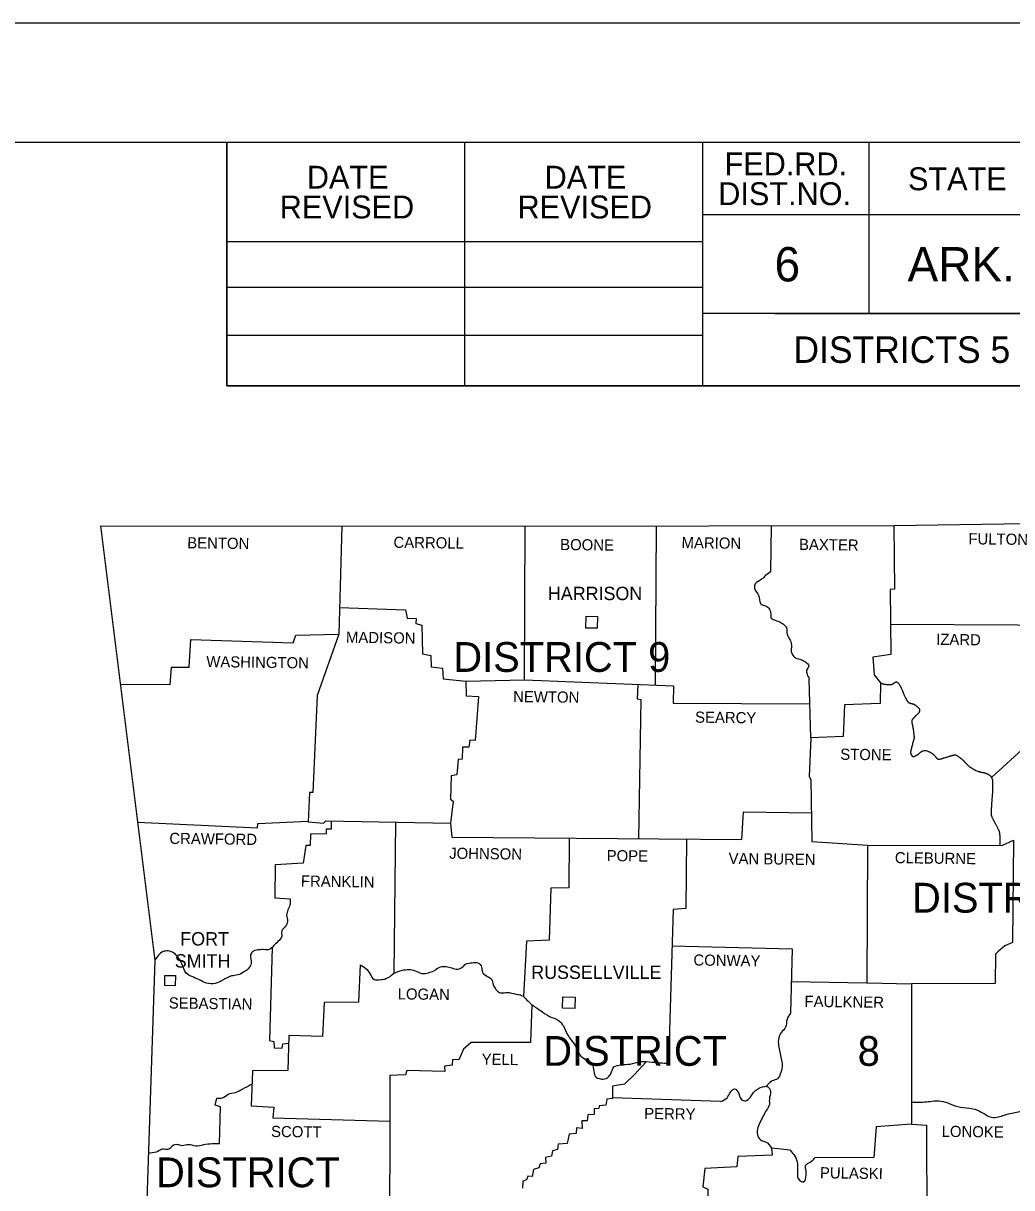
# Model space of a CAD drawing. Extents: x -819161 to 80911, y -6604 to 768454.
# Drawn here: x 48407 to 50478, y 8220 to 10660 of the extents above; entities that cross this region are included whole.
import ezdxf

# ---------------------------------------------------------------- set-up
doc = ezdxf.new("R2010")
doc.units = 0
for name, color, linetype in [('Default', 7, 'Continuous'), ('DSN_DRFT_Junk-No-Plot', 7, 'Continuous'), ('SHET_Annotations', 7, 'Continuous'), ('SHET_Border-Lines', 7, 'Continuous'), ('SHET_Border-Text', 7, 'Continuous')]:
    doc.layers.add(name, color=color, linetype=linetype)

msp = doc.modelspace()

# ---------------------------------------------------------------- linework, layer by layer
at = {"layer": 'Default'}
for p, q in [((49965.8, 8435), (49963.8, 8432.9)), ((48673, 8293.1), (48669, 8292.6))]:
    msp.add_line(p, q, dxfattribs=at)
for points in [[(35278.1, 10659.9), (35278.1, -340.1), (52278.1, -340.1), (52278.1, 10659.9)], [(49585.8, 9392.9), (49586.4, 9417.8), (49610, 9417.2), (49609.4, 9392.3)], [(48703.2, 8644.1), (48703.8, 8665.3), (48725.6, 8664.7), (48725, 8643.5)], [(49536.6, 8596.2), (49537.2, 8620.5), (49563.1, 8619.8), (49562.4, 8595.6)]]:
    msp.add_lwpolyline(points, close=True, dxfattribs=at)
for points in [[(48569, 9606.7), (49454.1, 9606.1), (50231.5, 9607.6), (51148, 9621.6), (51573.2, 9631.6)], [(50695.2, 9614.7), (50696.2, 9476.9), (50624.9, 9472.9), (50623, 9398.5), (50224.1, 9400.4)], [(48569, 9606.7), (48682.3, 8696.4), (48633.2, 7210.7)], [(49074.2, 9606.3), (49068.4, 9379.9)], [(49069.8, 9435.6), (49208, 9431.2), (49211.1, 9413.7), (49230.1, 9413.1), (49229.4, 9402.5), (49242.2, 9399.1), (49243.4, 9339.1), (49260.6, 9335.3), (49261.8, 9311.7), (49285.5, 9308.6), (49286.7, 9286.5), (49334, 9281.3), (49457.2, 9284.6), (49458.2, 9606.1)], [(49732.7, 9606.6), (49730.8, 9273.1)], [(49973.6, 9607.1), (49972.3, 9510.5)], [(50231.2, 9607.6), (50232.5, 9474.1), (50223.4, 9473.5), (50224.7, 9337.2), (50186.7, 9331.6), (50189.8, 9295.2), (50202.9, 9278.1), (50202, 9234.8), (50127.6, 9232), (50124.8, 9165.4), (50056.9, 9163.2), (50053.2, 9081.7), (50057.3, 9075.5), (50059.1, 8946), (50175.8, 8938.2), (50174.3, 8649.7), (50267.6, 8647.2), (50267.6, 8353.4), (50194.2, 8347.8), (50188.9, 8283.7), (50065.3, 8282.8)], [(48610.3, 9275.3), (48714.7, 9274.9), (48717.2, 9310.7), (48754.8, 9310.7), (48758.3, 9369.2), (48972.1, 9361.8), (48978.3, 9378), (49068.4, 9379.9), (49022.5, 9251.6), (49013.5, 9048.4), (49006.9, 9048.1), (49003.8, 8986.8), (49035.9, 8984), (49040.8, 8988.9), (49301.9, 8984), (49304.7, 8955)], [(49334, 9281.3), (49335.2, 9251), (49360.5, 9249.7), (49353.9, 9157.6), (49342.4, 9157.9), (49340.2, 9143.3), (49327.2, 9143), (49326.5, 9118.1), (49318.4, 9117.5), (49315.6, 9085.1), (49303.5, 9083.5), (49301.9, 9034.4), (49307.5, 9030.3), (49301.9, 8984)], [(49457.2, 9284.6), (49769.1, 9271.5), (49768.8, 9235.7), (50055.2, 9233.9)], [(49694.4, 9274.6), (49693.4, 9244.8), (49700.9, 9242.9), (49696.2, 8951.6)], [(50056.9, 9163.2), (50053.8, 9286.1)], [(50435.8, 9079.7), (50499.2, 9137.4), (50696.2, 9134.3), (50699.9, 9097.9), (50772.4, 9100.7)], [(49304.7, 8955), (49912.5, 8949.7), (49915.7, 9007.6), (50058.3, 9005.7)], [(48646.3, 8986.2), (48897.4, 8974.3), (48898.6, 8983.3), (49003.9, 8988.1)], [(49052.3, 8988.7), (49051.7, 8971.8), (49041.5, 8971.8), (49041.8, 8961.9), (49008.8, 8961.2), (49008.2, 8937), (48998.8, 8937), (48993.5, 8900.2), (48934.4, 8897.1), (48934.1, 8828), (48965.8, 8825.6)], [(49187.1, 8986.2), (49183.1, 8669.9)], [(49550.6, 8952.9), (49550, 8848.3), (49512.3, 8847.7), (49508.9, 8738.7), (49461, 8736.9), (49455.2, 8620.9)], [(49796.2, 8950.7), (49795.2, 8805.6), (49768.5, 8803.1), (49758.5, 8481)], [(50175.8, 8938.2), (50457.5, 8937), (50481.4, 8948.2), (50479.9, 8734.4), (50463.7, 8727.2), (50448.8, 8714.5), (50444.1, 8709.5), (50443.2, 8648.2), (50267.6, 8647.2)], [(48928.7, 8723.8), (48922.9, 8528.7), (48931.6, 8526.5), (48932.8, 8513.4), (48949.7, 8512.5), (48950.9, 8521.5), (48962.9, 8523.5)], [(49766.1, 8727.3), (50017.7, 8721), (50014.6, 8585.9)], [(49112.7, 8687.4), (49109, 8609.3), (49037.7, 8608.6), (49033.7, 8537.4), (48963.3, 8539.2), (48961.2, 8466.1), (48887.1, 8465.2), (48884.6, 8391.7), (48931.6, 8389.2), (48929.7, 8366.5), (49174.7, 8359.8)], [(50016.1, 8652.2), (50174.3, 8649.7)], [(49472.5, 8603.7), (49470, 8524.9), (49345.5, 8524.3), (49329, 8510.3), (49319.4, 8488.5), (49306, 8489.1), (49305.4, 8477), (49289.5, 8475.1), (49290.1, 8463.9), (49210.8, 8465.8), (49207.6, 8457.1), (49175, 8455.8), (49174.7, 8359.8)], [(49712.2, 8484.3), (49687.5, 8457.7), (49666.4, 8437.5), (49641.5, 8433.4), (49641.8, 8407.6), (49629.7, 8406), (49627.5, 8393), (49613.5, 8391.7), (49612.8, 8386.1), (49603.2, 8385.5), (49602.9, 8374), (49589.5, 8373.4), (49588.6, 8360.3), (49577.4, 8360.3), (49578, 8344.7), (49566.2, 8346), (49565.2, 8333.8), (49550.6, 8332.9), (49546.6, 8313), (49527.9, 8311.4), (49526, 8300.2), (49516.1, 8297.7), (49513.6, 8286.2), (49501.1, 8283.7), (49502.1, 8271.9), (49489.6, 8270.7), (49487.4, 8262), (49475.9, 8258.8), (49473.1, 8243.9), (49464.1, 8244.8), (49461.6, 8237.1), (49453.5, 8234.3), (49452.6, 8219.3)], [(48818.3, 8312.4), (48820.2, 8389.5), (48809, 8393.3), (48812.7, 8407.9)], [(49868, 8401.1), (49641.8, 8408.6)], [(49174.7, 8359.8), (49174, 8135.6), (49146.3, 8135), (49148.8, 8118.8), (49122.4, 8119.1), (49121.8, 8107), (49095.9, 8107), (49096.5, 8098.6), (49058.6, 8097.3), (49057.6, 8064), (49020.6, 8067.4), (49014.4, 7797.9)], [(50267.6, 8353.4), (50299.4, 8351.6), (50300, 8142.1), (50271.4, 8023.6), (50332.4, 8020.5), (50331.4, 7916)], [(50014, 8298.7), (49974.8, 8303.3), (49976.3, 8288.4), (49904.4, 8285.6), (49902.3, 8264.4), (49834.7, 8260.7), (49831, 8222.1), (49841, 8217.1), (49841, 8191.9)]]:
    msp.add_lwpolyline(points, dxfattribs=at)
for points in [[(49972.3, 9510.5), (49962.3, 9502.8), (49953.9, 9495), (49940.6, 9485.3), (49939, 9476.6), (49943.4, 9468.2), (49947.7, 9461), (49949.6, 9451.1), (49953.3, 9443), (49962.3, 9439.3), (49970.4, 9432.4), (49972.9, 9422.8), (49974.2, 9413.4), (49982.6, 9409.1), (49992.5, 9405.3), (50002.2, 9398.8), (50006.5, 9391), (50007.1, 9380.1), (50011.2, 9372.4), (50015.6, 9362.1), (50016.5, 9354), (50015.6, 9345.9), (50018, 9338.1), (50024.9, 9330.3), (50037.3, 9326.6), (50046.4, 9321.3), (50052.6, 9313.5), (50048.2, 9304.5), (50049.2, 9296.1), (50053.8, 9286.1)], [(48965.8, 8825.6), (48965.8, 8814), (48961.5, 8802.2), (48958.7, 8791.6), (48960.5, 8777.9), (48955.6, 8767), (48948.4, 8758), (48948.4, 8747.4), (48940.3, 8735.9), (48931.3, 8726.9), (48923.8, 8720.1), (48909.8, 8719.1), (48898.3, 8718.5), (48887.1, 8714.5), (48882.7, 8706), (48884.6, 8693.6), (48880.3, 8681.5), (48869.1, 8672.4), (48856.3, 8666.2), (48843.2, 8664), (48824.9, 8655.3), (48808.7, 8648.5), (48790.9, 8649.1), (48774.8, 8656.3), (48759.8, 8662.8), (48748.3, 8669.6), (48739.3, 8689.6), (48733.1, 8700.8), (48722.5, 8712), (48710.3, 8716.3), (48699.8, 8715.1), (48682.3, 8696.4)], [(49112.7, 8687.4), (49124.6, 8679.9), (49133.9, 8667.5), (49142, 8656.9), (49156, 8656.3), (49166.9, 8658.4), (49183.1, 8669.9)], [(49183.1, 8669.9), (49201.4, 8675.9), (49214.5, 8677.4), (49227.9, 8674.9), (49241.6, 8669.3), (49255.9, 8670.9), (49266.8, 8674.6), (49278, 8681.8), (49289.8, 8684), (49301.6, 8681.8), (49313.8, 8678.4), (49326.5, 8682.4), (49334.3, 8689.2), (49347.4, 8691.7), (49359.2, 8691.7), (49367.3, 8682.4), (49368.9, 8672.1), (49379.4, 8663.1), (49388.5, 8656.9), (49391.6, 8645.7), (49396.2, 8637.3), (49401.2, 8631.7), (49408.4, 8628.6), (49420.5, 8629.5), (49439.2, 8625.8), (49451, 8623.3), (49462.2, 8613.6), (49472.5, 8603.7)], [(49472.5, 8603.7), (49491.8, 8590.6), (49509.8, 8579.1), (49528.2, 8571), (49538.5, 8559.2), (49547.8, 8540.2), (49555.9, 8528.7), (49565.2, 8514.3), (49572.7, 8498.8), (49583.9, 8489.8), (49596, 8482.3), (49602, 8468.6), (49604.8, 8454.9), (49618.1, 8448.1), (49630.9, 8450.9), (49637.7, 8459.3), (49644.6, 8473.3), (49659.2, 8477.9), (49678.2, 8479.5), (49700, 8484.5), (49724.6, 8483.5), (49758.5, 8481)], [(50014.6, 8585.9), (50007.1, 8573.2), (50004.3, 8556.7), (49995.3, 8546.1), (49989.7, 8534.6), (49989.4, 8518.4), (49991.9, 8504.1), (49994.7, 8490.7), (49997.2, 8477.9), (49994.1, 8462.1), (49986.9, 8448.4), (49976.3, 8444.3), (49965.8, 8435)], [(48812.7, 8407.9), (48824.5, 8408.8), (48836.1, 8416.3), (48851.3, 8420), (48866.9, 8427.8), (48886.1, 8437.1)], [(49868, 8401.1), (49881.4, 8408.8), (49888.6, 8420.4), (49897.3, 8427.5), (49906, 8417.6), (49913.8, 8403.6), (49922.2, 8403.2), (49932.5, 8413.5), (49939, 8422.2), (49947.4, 8428.4), (49956.1, 8431.6), (49965.1, 8432.5), (49972.6, 8421.9), (49970.1, 8405.4), (49970.1, 8394.8), (49964.2, 8383), (49957.4, 8370.9), (49950.5, 8357.2), (49945.2, 8342.9), (49946.2, 8328.2), (49953.9, 8319.2), (49962.3, 8316.4), (49974.8, 8303.3)], [(50267.6, 8399.8), (50299.1, 8400.4), (50329.3, 8402), (50348.5, 8396.1), (50370.3, 8389.2), (50396.5, 8385.8), (50414.2, 8379), (50435.7, 8368.1), (50463.1, 8372.7), (50484.5, 8378), (50512.6, 8385.2), (50530.3, 8393.3), (50551.1, 8399.5), (50572, 8397), (50595.6, 8392.3), (50610.3, 8383.6), (50637.4, 8387.4), (50637.4, 8421.3)], [(48818.3, 8312.4), (48802.8, 8312.1), (48784.4, 8309.9), (48767.9, 8307.7), (48753.3, 8310.5), (48739.9, 8308.3), (48730.6, 8310.5), (48719, 8307.7), (48712.2, 8300.9), (48698.5, 8300.9), (48688.9, 8296.5), (48673, 8293.1)], [(50014, 8298.7), (50023.3, 8286.8), (50028.9, 8270.4), (50028.9, 8251.7), (50033, 8236.4), (50042, 8233), (50047.3, 8246.4), (50046.4, 8259.2), (50046.1, 8267.2), (50055.7, 8273.8), (50065.3, 8282.8)]]:
    msp.add_spline(points, degree=3, dxfattribs=at)
msp.add_open_spline([(50202.9, 9278.1), (50204.6, 9277.2), (50206.4, 9276.5), (50208.2, 9276.1), (50210.1, 9275.6), (50211.9, 9275.2), (50213.7, 9275), (50215.6, 9274.8), (50217.4, 9274.7), (50219.2, 9274.5), (50221.1, 9274.4), (50222.9, 9274.3), (50224.7, 9274.3), (50225.9, 9274.3), (50227.1, 9274.8), (50228.2, 9275.5), (50229.4, 9276.2), (50230.4, 9277.2), (50231.6, 9278), (50232.7, 9278.7), (50233.8, 9279.3), (50234.9, 9279.9), (50235.4, 9280.1), (50236, 9280.1), (50236.5, 9280), (50237.1, 9279.9), (50237.6, 9279.7), (50238.1, 9279.3), (50240.5, 9277.2), (50242.2, 9275.1), (50243.6, 9272.5), (50244.3, 9271.2), (50245, 9269.9), (50245.6, 9268.6), (50246.2, 9267.3), (50246.8, 9266), (50247.4, 9264.7), (50249, 9261.1), (50250.5, 9257.4), (50252.1, 9253.8), (50253.3, 9251.1), (50254.5, 9248.4), (50255.8, 9245.8), (50256.5, 9244.5), (50257.2, 9243.2), (50257.9, 9241.9), (50258.3, 9241.3), (50258.7, 9240.7), (50259.2, 9240), (50259.6, 9239.4), (50260, 9238.8), (50260.5, 9238.2), (50261.2, 9237.3), (50262.1, 9236.6), (50263.2, 9236.1), (50264.3, 9235.7), (50265.4, 9235.4), (50266.6, 9235.1), (50267.8, 9234.8), (50269, 9234.6), (50270.2, 9234.3), (50270.8, 9234.1), (50271.4, 9233.9), (50271.9, 9233.7), (50272.5, 9233.5), (50273, 9233.2), (50273.5, 9232.9), (50275.4, 9231.8), (50277.2, 9230.6), (50278.9, 9229.2), (50279.8, 9228.5), (50280.6, 9227.8), (50281.4, 9227), (50282.1, 9226.2), (50282.8, 9225.4), (50283.5, 9224.5), (50284, 9223.9), (50284.3, 9223.1), (50284.5, 9222.3), (50284.8, 9221.5), (50284.8, 9220.6), (50284.8, 9219.8), (50284.7, 9218.6), (50284.4, 9217.4), (50283.8, 9216.2), (50283.6, 9215.8), (50283.4, 9215.5), (50283.2, 9215.2), (50282.5, 9214.4), (50281.9, 9213.6), (50281.2, 9212.9), (50280.4, 9212.2), (50279.6, 9211.5), (50278.9, 9210.8), (50278.1, 9210.1), (50277.4, 9209.5), (50276.6, 9208.7), (50275.8, 9208), (50275.2, 9207.2), (50274.5, 9206.5), (50274.2, 9206.1), (50273.9, 9205.8), (50273.5, 9205.4), (50272.6, 9204.3), (50271.5, 9203.3), (50270.5, 9202.2), (50269.9, 9201.5), (50269.4, 9200.8), (50268.9, 9200), (50268.7, 9199.6), (50268.5, 9199.2), (50268.4, 9198.7), (50268.3, 9198.3), (50268.3, 9197.9), (50268.3, 9197.5), (50268.3, 9196.6), (50268.3, 9195.7), (50268.5, 9194.8), (50268.7, 9193.9), (50268.9, 9193.1), (50269.1, 9192.2), (50269.4, 9191.3), (50269.6, 9190.4), (50269.8, 9189.5), (50270.1, 9188.7), (50270.3, 9187.8), (50270.4, 9186.9), (50270.9, 9184.5), (50271.2, 9182.1), (50271.6, 9179.7), (50272, 9177.3), (50272.3, 9174.9), (50272.6, 9172.6), (50273.2, 9168.1), (50273.6, 9163.5), (50272.6, 9159.2), (50271.6, 9154.9), (50270.3, 9150.7), (50269.2, 9146.4), (50268.2, 9142.7), (50267.3, 9139), (50266.4, 9135.2), (50266.2, 9134.4), (50266.1, 9133.5), (50266.1, 9132.6), (50266.1, 9131.8), (50266.2, 9130.9), (50266.4, 9130), (50266.7, 9129.1), (50267, 9128.3), (50267.4, 9127.5), (50267.7, 9127), (50267.9, 9126.6), (50268.2, 9126.2), (50268.5, 9125.8), (50268.8, 9125.4), (50269.2, 9124.9), (50269.5, 9124.6), (50269.9, 9124.3), (50270.3, 9124), (50270.7, 9123.8), (50271.1, 9123.6), (50271.6, 9123.6), (50272.4, 9123.6), (50273.4, 9123.7), (50274.3, 9124), (50276.1, 9124.9), (50277.8, 9125.8), (50279.5, 9126.8), (50279.9, 9127.1), (50280.4, 9127.4), (50280.9, 9127.7), (50281.4, 9128), (50281.8, 9128.4), (50282.3, 9128.7), (50283.2, 9129.5), (50284, 9130.3), (50284.9, 9131.1), (50285.8, 9131.8), (50286.7, 9132.6), (50287.7, 9133.3), (50288.6, 9134), (50289.6, 9134.5), (50290.7, 9134.9), (50294.3, 9136.2), (50298.6, 9136.3), (50302.2, 9134.9), (50304.1, 9134.2), (50306, 9133.3), (50307.8, 9132.3), (50309.6, 9131.2), (50311.4, 9130.2), (50313.1, 9129), (50314.1, 9128.2), (50315.1, 9127.3), (50315.9, 9126.2), (50316.8, 9125.2), (50317.6, 9124), (50318.5, 9122.9), (50319.3, 9121.9), (50320.1, 9120.9), (50321.1, 9119.9), (50321.5, 9119.5), (50322, 9119.2), (50322.6, 9118.9), (50322.8, 9118.8), (50323.1, 9118.7), (50323.4, 9118.6), (50323.7, 9118.5), (50324, 9118.4), (50324.3, 9118.4), (50326.2, 9118.2), (50328.2, 9118.3), (50330, 9118.9), (50332, 9119.4), (50333.9, 9120), (50335.8, 9120.6), (50339, 9121.6), (50342.2, 9122.7), (50345.4, 9123.7), (50347.6, 9124.4), (50349.8, 9125.1), (50352, 9125.8), (50353, 9126.1), (50354.1, 9126.3), (50355.2, 9126.6), (50355.8, 9126.7), (50356.3, 9126.8), (50356.9, 9126.9), (50357.4, 9127), (50358, 9127.1), (50358.5, 9127.1), (50360.2, 9127.2), (50361.9, 9126.7), (50363.3, 9125.7), (50364.9, 9124.6), (50366.4, 9123.6), (50367.8, 9122.5), (50369.2, 9121.4), (50370.6, 9120.4), (50372, 9119.3), (50373.4, 9118.2), (50374.7, 9117.1), (50375.9, 9115.9), (50376.8, 9115.1), (50377.7, 9114.3), (50378.5, 9113.4), (50379.3, 9112.5), (50380.1, 9111.6), (50380.9, 9110.8), (50381.7, 9109.9), (50382.5, 9109), (50383.3, 9108.1), (50384.1, 9107.3), (50385, 9106.5), (50385.9, 9105.6), (50388.8, 9103), (50391.9, 9100.8), (50395.2, 9098.8), (50399, 9096.5), (50402.9, 9094.5), (50407.1, 9092.9), (50408.3, 9092.4), (50409.5, 9092), (50410.7, 9091.7), (50412, 9091.5), (50413.2, 9091.2), (50414.5, 9090.9), (50415.7, 9090.7), (50417, 9090.5), (50418.3, 9090.2), (50419.5, 9090), (50420.8, 9089.5), (50422, 9089.2), (50424.7, 9088.3), (50427.3, 9087.2), (50429.8, 9085.8), (50431, 9085.1), (50432.1, 9084.3), (50433.1, 9083.3), (50433.6, 9082.8), (50434.1, 9082.3), (50434.5, 9081.7), (50434.7, 9081.4), (50434.9, 9081.1), (50435.1, 9080.8), (50435.3, 9080.5), (50435.5, 9080.1), (50435.7, 9079.8), (50436, 9079.2), (50436.3, 9078.5), (50436.5, 9077.9), (50437.2, 9075.9), (50437.7, 9073.9), (50437.8, 9071.9), (50437.9, 9070.6), (50437.9, 9069.3), (50437.9, 9067.9), (50437.9, 9066.6), (50437.9, 9065.3), (50437.9, 9063.9), (50437.8, 9061.7), (50437.8, 9059.4), (50437.8, 9057.1), (50437.8, 9054.8), (50437.7, 9052.5), (50437.6, 9050.2), (50437.2, 9044.5), (50436.7, 9038.8), (50436.3, 9033.1), (50435.9, 9027), (50435.5, 9020.9), (50435.1, 9014.8), (50435, 9013.2), (50434.8, 9011.7), (50434.7, 9010.1), (50434.6, 9008.6), (50434.6, 9007), (50434.6, 9005.5), (50434.6, 9003.9), (50434.8, 9002.4), (50435.1, 9000.9), (50435.5, 8999.3), (50435.9, 8997.8), (50436.6, 8996.4), (50437.6, 8994.4), (50438.7, 8992.4), (50439.7, 8990.4), (50440.8, 8988.5), (50441.8, 8986.5), (50442.8, 8984.6), (50444.1, 8982.2), (50445.3, 8979.8), (50446.6, 8977.4), (50447.8, 8975.1), (50449.1, 8972.7), (50450.3, 8970.3), (50451.3, 8968.2), (50451.9, 8966), (50452.2, 8963.7), (50452.4, 8962.6), (50452.5, 8961.5), (50452.6, 8960.3), (50452.7, 8959.2), (50452.7, 8958), (50452.8, 8956.9), (50453, 8953.6), (50453.1, 8950.2), (50453.1, 8946.9), (50453, 8943.6), (50452.8, 8940.3), (50452.3, 8937)], degree=3, dxfattribs=at)
at = {"layer": 'DSN_DRFT_Junk-No-Plot'}
msp.add_lwpolyline([(35278.1, -340.1), (52278.1, -340.1), (52278.1, 10659.9), (35278.1, 10659.9)], close=True, dxfattribs=at)
at = {"layer": 'SHET_Border-Lines'}
for p, q in [((48833.5, 9900.4), (48833.5, 10409.9)), ((49331.8, 9900.4), (49331.8, 10409.9)), ((49830, 10409.9), (49830, 9900.4)), ((50178.9, 10409.9), (50178.9, 10052)), ((52028.1, 10258.3), (49830, 10258.3)), ((48833.5, 10202.6), (49830, 10202.6)), ((48833.5, 10106.7), (49830, 10106.7)), ((52028.1, 10052), (49830, 10052)), ((49981, 10052), (52028.1, 10052)), ((48833.5, 10006.7), (49830, 10006.7)), ((52028.1, 9900.4), (48833.5, 9900.4))]:
    msp.add_line(p, q, dxfattribs=at)
for points in [[(35528.1, -90.1), (52028.1, -90.1), (52028.1, 10409.9), (35528.1, 10409.9)], [(35528.1, -90.1), (52028.1, -90.1), (52028.1, 10409.9), (35528.1, 10409.9)], [(48833.5, 9900.4), (52028.1, 9900.4), (52028.1, 10409.9), (48833.5, 10409.9)]]:
    msp.add_lwpolyline(points, close=True, dxfattribs=at)

# ---------------------------------------------------------------- texts
at = {"layer": 'Default'}
for s, rotation, p in [('FULTON', 359.282, (50387.1, 9568.4)), ('BENTON', 359.2874, (48750.4, 9560)), ('CARROLL', 359.267, (49182.5, 9561)), ('BOONE', 359.3139, (49531.7, 9556.3)), ('MARION', 359.2237, (49786.1, 9560.4)), ('BAXTER', 359.2892, (50032.2, 9556.6)), ('MADISON', 359.217, (49082.9, 9362.1)), ('IZARD', 359.1987, (50319.5, 9357.8)), ('WASHINGTON', 359.2079, (48790.3, 9311.1)), ('NEWTON', 359.303, (49433.2, 9237.9)), ('SEARCY', 359.2838, (49814.4, 9194.7)), ('STONE', 359.3139, (50118.6, 9116.9)), ('CRAWFORD', 359.2748, (48712.9, 8940.7)), ('JOHNSON', 359.2575, (49299.2, 8909.6)), ('POPE', 359.3389, (49629.2, 8904.6)), ('VAN BUREN', 359.2547, (49884.6, 8898.7)), ('CLEBURNE', 359.2518, (50233, 8900.3)), ('FRANKLIN', 359.1782, (48988.5, 8851.4)), ('CONWAY', 359.1737, (49810.9, 8685.9)), ('LOGAN', 359.3076, (49191.3, 8614.9)), ('SEBASTIAN', 359.1959, (48711.7, 8595.9)), ('FAULKNER', 359.2447, (50043.7, 8599.3)), ('YELL', 359.3097, (49367.2, 8478)), ('PERRY', 359.2992, (49707.8, 8364.4)), ('SCOTT', 359.32, (48926, 8326.7)), ('LONOKE', 359.2784, (50331, 8327)), ('PULASKI', 359.1854, (50076, 8240.2))]:
    msp.add_text(s, height=23.34, rotation=rotation, dxfattribs=at).set_placement(p)
for s, height, p in [('HARRISON', 28.01, (49506.1, 9451.4)), ('DISTRICT 9', 62.43, (49308, 9301.1)), ('DISTRICT', 62.43, (50269.1, 8796.7)), ('FORT', 28.01, (48735.9, 8727.8)), ('SMITH', 28.01, (48724.3, 8681.5)), ('RUSSELLVILLE', 28.009, (49471.2, 8657.8)), ('DISTRICT', 62.43, (49496.4, 8475.8)), ('8', 62.4, (50155.2, 8475.7)), ('DISTRICT', 62.43, (48685.1, 8221.4))]:
    msp.add_text(s, height=height, dxfattribs=at).set_placement(p)
at = {"layer": 'SHET_Annotations'}
for s, height, p in [('6', 72, (49981, 10119.1)), ('ARK.', 72, (50259.7, 10119.1)), ('DISTRICTS 5 & 9 PAVEMENT FRICTION IMPVTS. (HFST) (S)', 55.578, (50020.6, 9948.4))]:
    msp.add_text(s, height=height, dxfattribs=at).set_placement(p)
at = {"layer": 'SHET_Border-Text'}
for s, p in [('FED.RD.', (49876.2, 10341.3)), ('DATE', (49001.1, 10313.4)), ('DATE', (49499.3, 10313.4)), ('STATE', (50260.6, 10310.1)), ('DIST.NO.', (49863.1, 10278.9)), ('REVISED', (48944.2, 10251)), ('REVISED', (49442.5, 10251))]:
    msp.add_text(s, height=48, dxfattribs=at).set_placement(p)

doc.saveas('drawing.dxf')
